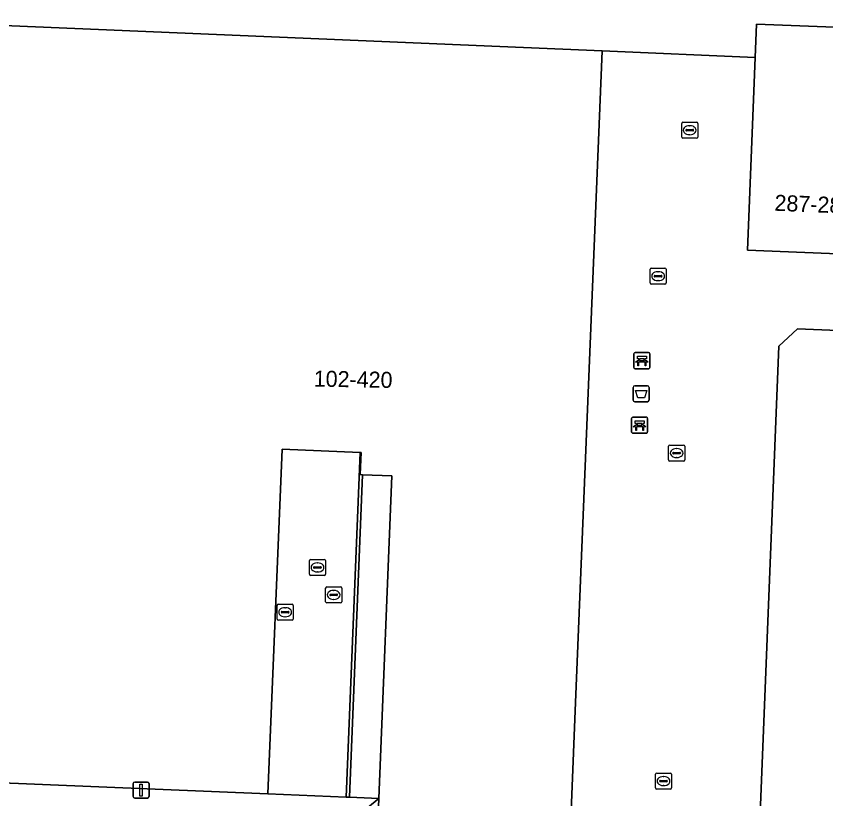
# Model space of a CAD drawing. Extents: x 160888 to 161385, y 386490 to 386908.
# Drawn here: x 161090.9 to 161141.4, y 386663.9 to 386712.7 of the extents above; entities that cross this region are included whole.
import ezdxf

# ---------------------------------------------------------------- set-up
doc = ezdxf.new("R2010")
doc.units = 0
for name, color, linetype in [('IMGEO_Afvalbak', 7, 'Continuous'), ('IMGEO_Bank', 7, 'Continuous'), ('IMGEO_Brandkraan', 7, 'Continuous'), ('IMGEO_Kolk', 7, 'Continuous'), ('IMGEO_Lichtmast', 7, 'Continuous'), ('IMGEO_Pand', 7, 'Continuous'), ('IMGEO_Pand_nummerreeks', 7, 'Continuous'), ('IMGEO_Rijbaan_lokaal_gesloten', 7, 'Continuous'), ('IMGEO_Rioolput', 7, 'Continuous'), ('IMGEO_Voetgangersgebied_open', 7, 'Continuous'), ('IMGEO_Voetpad_open', 7, 'Continuous')]:
    doc.layers.add(name, color=color, linetype=linetype)

msp = doc.modelspace()

# ---------------------------------------------------------------- linework, layer by layer
at = {"layer": 'IMGEO_Afvalbak'}
for p, q in [((161129.39, 386688.722), (161129.39, 386689.522)), ((161129.39, 386689.522), (161129.39, 386688.722)), ((161129.49, 386689.622), (161130.28, 386689.622)), ((161130.28, 386689.622), (161129.49, 386689.622)), ((161130.38, 386689.522), (161130.38, 386688.722)), ((161130.38, 386688.722), (161130.38, 386689.522)), ((161130.28, 386688.622), (161129.49, 386688.622)), ((161129.49, 386688.622), (161130.28, 386688.622))]:
    msp.add_line(p, q, dxfattribs=at)
msp.add_lwpolyline([(161129.533, 386689.336), (161130.237, 386689.336), (161130.088, 386688.866), (161129.682, 386688.866), (161129.533, 386689.336)], dxfattribs=at)
for centre, start, end in [((161129.49, 386689.522), 90, 180), ((161129.49, 386689.522), 90, 180), ((161130.28, 386689.522), 0, 90), ((161130.28, 386689.522), 360, 90), ((161129.49, 386688.722), 180, 270), ((161129.49, 386688.722), 180, 270), ((161130.28, 386688.722), 270, 0), ((161130.28, 386688.722), 270, 0)]:
    msp.add_arc(centre, 0.1, start, end, dxfattribs=at)
at = {"layer": 'IMGEO_Bank'}
for p, q in [((161129.508, 386691.686), (161130.349, 386691.686)), ((161130.349, 386691.686), (161129.508, 386691.686)), ((161129.433, 386690.761), (161129.433, 386691.602)), ((161129.433, 386691.602), (161129.433, 386690.761)), ((161129.742, 386691.192), (161129.742, 386691.298)), ((161129.786, 386691.298), (161129.786, 386691.192)), ((161130.074, 386691.304), (161129.792, 386691.304)), ((161129.792, 386691.186), (161130.074, 386691.186)), ((161130.08, 386691.192), (161130.08, 386691.298)), ((161130.124, 386691.298), (161130.124, 386691.192)), ((161130.433, 386691.611), (161130.433, 386690.77)), ((161130.433, 386690.77), (161130.433, 386691.611)), ((161130.358, 386690.686), (161129.517, 386690.686)), ((161129.517, 386690.686), (161130.358, 386690.686)), ((161130.13, 386691.084), (161129.737, 386691.084)), ((161129.366, 386687.659), (161130.207, 386687.659)), ((161130.207, 386687.659), (161129.366, 386687.659)), ((161129.291, 386686.734), (161129.291, 386687.575)), ((161129.291, 386687.575), (161129.291, 386686.734)), ((161129.6, 386687.165), (161129.6, 386687.271)), ((161129.644, 386687.271), (161129.644, 386687.165)), ((161129.932, 386687.277), (161129.65, 386687.277)), ((161129.65, 386687.159), (161129.932, 386687.159)), ((161129.938, 386687.165), (161129.938, 386687.271)), ((161129.982, 386687.271), (161129.982, 386687.165)), ((161130.291, 386687.584), (161130.291, 386686.743)), ((161130.291, 386686.743), (161130.291, 386687.584)), ((161130.216, 386686.659), (161129.375, 386686.659)), ((161129.375, 386686.659), (161130.216, 386686.659)), ((161129.988, 386687.057), (161129.595, 386687.057))]:
    msp.add_line(p, q, dxfattribs=at)
for points in [[(161129.68, 386691.084), (161129.538, 386691.084), (161129.65, 386691.186), (161129.736, 386691.186)], [(161129.736, 386691.304), (161129.65, 386691.304), (161129.65, 386691.465), (161130.213, 386691.465), (161130.213, 386691.304), (161130.13, 386691.304)], [(161130.13, 386691.186), (161130.213, 386691.186), (161130.325, 386691.084), (161130.186, 386691.084)], [(161129.73, 386691.077), (161129.73, 386690.87), (161129.687, 386690.87), (161129.687, 386691.077)], [(161130.18, 386691.077), (161130.18, 386690.87), (161130.136, 386690.87), (161130.136, 386691.077)], [(161129.538, 386687.057), (161129.396, 386687.057), (161129.508, 386687.159), (161129.594, 386687.159)], [(161129.594, 386687.277), (161129.508, 386687.277), (161129.508, 386687.438), (161130.071, 386687.438), (161130.071, 386687.277), (161129.988, 386687.277)], [(161129.988, 386687.159), (161130.071, 386687.159), (161130.183, 386687.057), (161130.044, 386687.057)], [(161129.588, 386687.05), (161129.588, 386686.843), (161129.545, 386686.843), (161129.545, 386687.05)], [(161130.038, 386687.05), (161130.038, 386686.843), (161129.994, 386686.843), (161129.994, 386687.05)]]:
    msp.add_lwpolyline(points, dxfattribs=at)
for centre, radius, start, end in [((161129.511, 386691.608), 0.0779, 92.4484, 184.2845), ((161129.511, 386691.608), 0.0779, 92.4484, 184.2845), ((161130.355, 386691.608), 0.0779, 2.4484, 94.2845), ((161130.355, 386691.608), 0.0779, 2.4484, 94.2845), ((161129.735, 386691.297), 0.00671, 2.8957, 87.1043), ((161129.735, 386691.193), 0.00671, 272.8957, 357.1043), ((161129.792, 386691.297), 0.00671, 92.8957, 177.1043), ((161129.792, 386691.193), 0.00671, 182.8957, 267.1043), ((161130.074, 386691.297), 0.00671, 2.8957, 87.1043), ((161130.074, 386691.193), 0.00671, 272.8957, 357.1043), ((161130.131, 386691.297), 0.00671, 92.8957, 177.1043), ((161130.131, 386691.193), 0.00671, 182.8957, 267.1043), ((161129.511, 386690.764), 0.0779, 182.4484, 274.2845), ((161129.511, 386690.764), 0.0779, 182.4484, 274.2845), ((161129.68, 386691.077), 0.00671, 2.8957, 87.1043), ((161129.737, 386691.077), 0.00671, 92.8957, 177.1043), ((161130.129, 386691.077), 0.00671, 2.8957, 87.1043), ((161130.186, 386691.077), 0.00671, 92.8957, 177.1043), ((161130.355, 386690.764), 0.0779, 272.4484, 4.2845), ((161130.355, 386690.764), 0.0779, 272.4484, 4.2845), ((161129.369, 386687.581), 0.0779, 92.4484, 184.2845), ((161129.369, 386687.581), 0.0779, 92.4484, 184.2845), ((161130.213, 386687.581), 0.0779, 2.4484, 94.2845), ((161130.213, 386687.581), 0.0779, 2.4484, 94.2845), ((161129.593, 386687.27), 0.00671, 2.8957, 87.1043), ((161129.593, 386687.166), 0.00671, 272.8957, 357.1043), ((161129.65, 386687.27), 0.00671, 92.8957, 177.1043), ((161129.65, 386687.166), 0.00671, 182.8957, 267.1043), ((161129.932, 386687.27), 0.00671, 2.8957, 87.1043), ((161129.932, 386687.166), 0.00671, 272.8957, 357.1043), ((161129.989, 386687.27), 0.00671, 92.8957, 177.1043), ((161129.989, 386687.166), 0.00671, 182.8957, 267.1043), ((161129.369, 386686.737), 0.0779, 182.4484, 274.2845), ((161129.369, 386686.737), 0.0779, 182.4484, 274.2845), ((161129.538, 386687.05), 0.00671, 2.8957, 87.1043), ((161129.595, 386687.05), 0.00671, 92.8957, 177.1043), ((161129.987, 386687.05), 0.00671, 2.8957, 87.1043), ((161130.044, 386687.05), 0.00671, 92.8957, 177.1043), ((161130.213, 386686.737), 0.0779, 272.4484, 4.2845), ((161130.213, 386686.737), 0.0779, 272.4484, 4.2845)]:
    msp.add_arc(centre, radius, start, end, dxfattribs=at)
at = {"layer": 'IMGEO_Brandkraan'}
for p, q in [((161109.214, 386677.871), (161109.214, 386678.723)), ((161109.289, 386678.797), (161110.141, 386678.797)), ((161109.702, 386678.577), (161109.727, 386678.577)), ((161110.215, 386678.723), (161110.215, 386677.871)), ((161109.473, 386678.291), (161109.473, 386678.303)), ((161109.911, 386678.254), (161109.513, 386678.254)), ((161109.516, 386678.34), (161109.914, 386678.34)), ((161109.957, 386678.303), (161109.957, 386678.291)), ((161110.141, 386677.797), (161109.289, 386677.797)), ((161109.725, 386678.017), (161109.7, 386678.017))]:
    msp.add_line(p, q, dxfattribs=at)
for points in [[(161109.214, 386677.871), (161109.214, 386678.723)], [(161109.289, 386678.797), (161110.141, 386678.797)], [(161110.215, 386678.723), (161110.215, 386677.871)], [(161110.141, 386677.797), (161109.289, 386677.797)]]:
    msp.add_lwpolyline(points, dxfattribs=at)
for centre, radius, start, end in [((161109.291, 386678.721), 0.0765, 91.552, 178.448), ((161109.291, 386678.721), 0.0765, 91.552, 178.448), ((161110.139, 386678.721), 0.0765, 1.552, 88.448), ((161110.139, 386678.721), 0.0765, 1.552, 88.448), ((161109.513, 386678.3), 0.0403, 85.8775, 175.7526), ((161109.51, 386678.29), 0.0366, 178.938, 274.7102), ((161109.914, 386678.297), 0.043, 264.8664, 352.4533), ((161109.918, 386678.302), 0.0386, 1.7309, 96.639), ((161109.291, 386677.873), 0.0765, 181.552, 268.448), ((161109.291, 386677.873), 0.0765, 181.552, 268.448), ((161110.139, 386677.873), 0.0765, 271.552, 358.448), ((161110.139, 386677.873), 0.0765, 271.552, 358.448)]:
    msp.add_arc(centre, radius, start, end, dxfattribs=at)
for centre, major_axis, ratio, start_param, end_param in [((161109.701, 386678.297), (-0.387, 0.002), 0.722429, 4.712389, 7.853982), ((161109.726, 386678.297), (-0.39, 0.002), 0.717154, 1.570796, 4.712389)]:
    msp.add_ellipse(centre, major_axis=major_axis, ratio=ratio, start_param=start_param, end_param=end_param, dxfattribs=at)
at = {"layer": 'IMGEO_Kolk'}
for p, q in [((161132.412, 386705.126), (161132.412, 386705.978)), ((161132.487, 386706.052), (161133.339, 386706.052)), ((161132.9, 386705.832), (161132.925, 386705.832)), ((161133.413, 386705.978), (161133.413, 386705.126)), ((161132.671, 386705.546), (161132.671, 386705.558)), ((161133.109, 386705.509), (161132.711, 386705.509)), ((161132.714, 386705.595), (161133.112, 386705.595)), ((161132.923, 386705.272), (161132.898, 386705.272)), ((161133.155, 386705.558), (161133.155, 386705.546)), ((161133.339, 386705.052), (161132.487, 386705.052)), ((161131.599, 386685.001), (161131.599, 386685.853)), ((161131.674, 386685.927), (161132.526, 386685.927)), ((161132.087, 386685.707), (161132.112, 386685.707)), ((161132.6, 386685.853), (161132.6, 386685.001)), ((161131.858, 386685.421), (161131.858, 386685.433)), ((161132.296, 386685.384), (161131.898, 386685.384)), ((161131.901, 386685.47), (161132.299, 386685.47)), ((161132.11, 386685.147), (161132.085, 386685.147)), ((161132.342, 386685.433), (161132.342, 386685.421)), ((161132.526, 386684.927), (161131.674, 386684.927)), ((161110.225, 386676.161), (161110.225, 386677.013)), ((161110.3, 386677.087), (161111.152, 386677.087)), ((161111.226, 386677.013), (161111.226, 386676.161)), ((161110.484, 386676.581), (161110.484, 386676.593)), ((161110.922, 386676.544), (161110.524, 386676.544)), ((161110.527, 386676.63), (161110.925, 386676.63)), ((161110.713, 386676.867), (161110.738, 386676.867)), ((161110.968, 386676.593), (161110.968, 386676.581)), ((161111.152, 386676.087), (161110.3, 386676.087)), ((161110.736, 386676.307), (161110.711, 386676.307)), ((161130.854, 386665.48), (161131.706, 386665.48)), ((161130.779, 386664.554), (161130.779, 386665.406)), ((161131.038, 386664.974), (161131.038, 386664.986)), ((161131.476, 386664.937), (161131.078, 386664.937)), ((161131.081, 386665.023), (161131.479, 386665.023)), ((161131.267, 386665.26), (161131.292, 386665.26)), ((161131.522, 386664.986), (161131.522, 386664.974)), ((161131.78, 386665.406), (161131.78, 386664.554)), ((161131.706, 386664.48), (161130.854, 386664.48)), ((161131.29, 386664.7), (161131.265, 386664.7))]:
    msp.add_line(p, q, dxfattribs=at)
for points in [[(161132.412, 386705.126), (161132.412, 386705.978)], [(161132.487, 386706.052), (161133.339, 386706.052)], [(161133.413, 386705.978), (161133.413, 386705.126)], [(161133.339, 386705.052), (161132.487, 386705.052)], [(161131.599, 386685.001), (161131.599, 386685.853)], [(161131.674, 386685.927), (161132.526, 386685.927)], [(161132.6, 386685.853), (161132.6, 386685.001)], [(161132.526, 386684.927), (161131.674, 386684.927)], [(161110.225, 386676.161), (161110.225, 386677.013)], [(161110.3, 386677.087), (161111.152, 386677.087)], [(161111.226, 386677.013), (161111.226, 386676.161)], [(161111.152, 386676.087), (161110.3, 386676.087)], [(161130.854, 386665.48), (161131.706, 386665.48)], [(161130.779, 386664.554), (161130.779, 386665.406)], [(161131.78, 386665.406), (161131.78, 386664.554)], [(161131.706, 386664.48), (161130.854, 386664.48)]]:
    msp.add_lwpolyline(points, dxfattribs=at)
for centre, radius, start, end in [((161132.489, 386705.976), 0.0765, 91.552, 178.448), ((161132.489, 386705.976), 0.0765, 91.552, 178.448), ((161133.337, 386705.976), 0.0765, 1.552, 88.448), ((161133.337, 386705.976), 0.0765, 1.552, 88.448), ((161132.711, 386705.555), 0.0403, 85.8775, 175.7526), ((161132.708, 386705.545), 0.0366, 178.938, 274.7102), ((161133.112, 386705.552), 0.043, 264.8664, 352.4533), ((161133.116, 386705.557), 0.0386, 1.7309, 96.639), ((161132.489, 386705.128), 0.0765, 181.552, 268.448), ((161132.489, 386705.128), 0.0765, 181.552, 268.448), ((161133.337, 386705.128), 0.0765, 271.552, 358.448), ((161133.337, 386705.128), 0.0765, 271.552, 358.448), ((161131.676, 386685.851), 0.0765, 91.552, 178.448), ((161131.676, 386685.851), 0.0765, 91.552, 178.448), ((161132.524, 386685.851), 0.0765, 1.552, 88.448), ((161132.524, 386685.851), 0.0765, 1.552, 88.448), ((161131.898, 386685.43), 0.0403, 85.8775, 175.7526), ((161131.895, 386685.42), 0.0366, 178.938, 274.7102), ((161132.299, 386685.427), 0.043, 264.8664, 352.4533), ((161132.303, 386685.432), 0.0386, 1.7309, 96.639), ((161131.676, 386685.003), 0.0765, 181.552, 268.448), ((161131.676, 386685.003), 0.0765, 181.552, 268.448), ((161132.524, 386685.003), 0.0765, 271.552, 358.448), ((161132.524, 386685.003), 0.0765, 271.552, 358.448), ((161110.302, 386677.011), 0.0765, 91.552, 178.448), ((161110.302, 386677.011), 0.0765, 91.552, 178.448), ((161111.15, 386677.011), 0.0765, 1.552, 88.448), ((161111.15, 386677.011), 0.0765, 1.552, 88.448), ((161110.524, 386676.59), 0.0403, 85.8775, 175.7526), ((161110.521, 386676.58), 0.0366, 178.938, 274.7102), ((161110.925, 386676.587), 0.043, 264.8664, 352.4533), ((161110.929, 386676.592), 0.0386, 1.7309, 96.639), ((161110.302, 386676.163), 0.0765, 181.552, 268.448), ((161110.302, 386676.163), 0.0765, 181.552, 268.448), ((161111.15, 386676.163), 0.0765, 271.552, 358.448), ((161111.15, 386676.163), 0.0765, 271.552, 358.448), ((161130.856, 386665.404), 0.0765, 91.552, 178.448), ((161130.856, 386665.404), 0.0765, 91.552, 178.448), ((161131.704, 386665.404), 0.0765, 1.552, 88.448), ((161131.704, 386665.404), 0.0765, 1.552, 88.448), ((161131.078, 386664.983), 0.0403, 85.8775, 175.7526), ((161131.075, 386664.973), 0.0366, 178.938, 274.7102), ((161131.479, 386664.98), 0.043, 264.8664, 352.4533), ((161131.483, 386664.985), 0.0386, 1.7309, 96.639), ((161130.856, 386664.556), 0.0765, 181.552, 268.448), ((161130.856, 386664.556), 0.0765, 181.552, 268.448), ((161131.704, 386664.556), 0.0765, 271.552, 358.448), ((161131.704, 386664.556), 0.0765, 271.552, 358.448)]:
    msp.add_arc(centre, radius, start, end, dxfattribs=at)
for centre, major_axis, ratio, start_param, end_param in [((161132.899, 386705.552), (-0.387, 0.002), 0.722429, 4.712389, 7.853982), ((161132.924, 386705.552), (-0.39, 0.002), 0.717154, 1.570796, 4.712389), ((161132.086, 386685.427), (-0.387, 0.002), 0.722429, 4.712389, 7.853982), ((161132.111, 386685.427), (-0.39, 0.002), 0.717154, 1.570796, 4.712389), ((161110.712, 386676.587), (-0.387, 0.002), 0.722429, 4.712389, 7.853982), ((161110.737, 386676.587), (-0.39, 0.002), 0.717154, 1.570796, 4.712389), ((161131.266, 386664.98), (-0.387, 0.002), 0.722429, 4.712389, 7.853982), ((161131.291, 386664.98), (-0.39, 0.002), 0.717154, 1.570796, 4.712389)]:
    msp.add_ellipse(centre, major_axis=major_axis, ratio=ratio, start_param=start_param, end_param=end_param, dxfattribs=at)
at = {"layer": 'IMGEO_Lichtmast'}
for p, q in [((161098.328, 386664.921), (161099.118, 386664.921)), ((161099.118, 386664.921), (161098.328, 386664.921)), ((161098.228, 386664.021), (161098.228, 386664.821)), ((161098.228, 386664.821), (161098.228, 386664.021)), ((161099.218, 386664.821), (161099.218, 386664.021)), ((161099.218, 386664.021), (161099.218, 386664.821)), ((161099.118, 386663.921), (161098.328, 386663.921)), ((161098.328, 386663.921), (161099.118, 386663.921))]:
    msp.add_line(p, q, dxfattribs=at)
msp.add_lwpolyline([(161098.648, 386664.796), (161098.798, 386664.796), (161098.798, 386664.046), (161098.648, 386664.046), (161098.648, 386664.796)], dxfattribs=at)
for centre, start, end in [((161098.328, 386664.821), 90, 180), ((161098.328, 386664.821), 90, 180), ((161099.118, 386664.821), 0, 90), ((161099.118, 386664.821), 360, 90), ((161098.328, 386664.021), 180, 270), ((161098.328, 386664.021), 180, 270), ((161099.118, 386664.021), 270, 0), ((161099.118, 386664.021), 270, 0)]:
    msp.add_arc(centre, 0.1, start, end, dxfattribs=at)
at = {"layer": 'IMGEO_Pand'}
for points in [[(161125.316, 386657.891), (161125.805, 386669.885), (161127.462, 386710.495), (161080.851, 386712.475), (161066.929, 386705.356), (161066.624, 386705.366), (161065.189, 386671.013), (161064.976, 386665.921), (161106.621, 386664.183), (161107.513, 386685.669), (161112.376, 386685.455), (161112.436, 386685.452), (161112.38, 386684.082), (161112.521, 386684.076), (161114.357, 386684.004), (161113.546, 386663.894), (161112.853, 386646.718)], [(161152.718, 386692.638), (161139.631, 386693.169), (161138.466, 386692.089), (161136.014, 386630.69), (161144.239, 386630.361)]]:
    msp.add_lwpolyline(points, dxfattribs=at)
msp.add_lwpolyline([(161147.81, 386709.63), (161147.892, 386711.738), (161137.065, 386712.159), (161136.985, 386710.09), (161136.801, 386705.368), (161136.518, 386698.078), (161143.664, 386697.789), (161147.34, 386697.641), (161147.455, 386700.577)], close=True, dxfattribs=at)
at = {"layer": 'IMGEO_Rijbaan_lokaal_gesloten'}
msp.add_lwpolyline([(161112.376, 386685.455), (161107.513, 386685.669), (161106.621, 386664.183), (161111.51, 386663.979)], close=True, dxfattribs=at)
at = {"layer": 'IMGEO_Rioolput'}
for p, q in [((161130.444, 386696.027), (161130.444, 386696.879)), ((161130.519, 386696.953), (161131.371, 386696.953)), ((161130.932, 386696.733), (161130.957, 386696.733)), ((161131.445, 386696.879), (161131.445, 386696.027)), ((161130.703, 386696.447), (161130.703, 386696.459)), ((161131.141, 386696.41), (161130.743, 386696.41)), ((161130.746, 386696.496), (161131.144, 386696.496)), ((161131.187, 386696.459), (161131.187, 386696.447)), ((161131.371, 386695.953), (161130.519, 386695.953)), ((161130.955, 386696.173), (161130.93, 386696.173)), ((161107.276, 386676.009), (161108.128, 386676.009)), ((161107.201, 386675.083), (161107.201, 386675.935)), ((161107.46, 386675.503), (161107.46, 386675.515)), ((161107.503, 386675.552), (161107.901, 386675.552)), ((161107.689, 386675.789), (161107.714, 386675.789)), ((161107.944, 386675.515), (161107.944, 386675.503)), ((161108.202, 386675.935), (161108.202, 386675.083)), ((161108.128, 386675.009), (161107.276, 386675.009)), ((161107.898, 386675.466), (161107.5, 386675.466)), ((161107.712, 386675.229), (161107.687, 386675.229))]:
    msp.add_line(p, q, dxfattribs=at)
for points in [[(161130.444, 386696.027), (161130.444, 386696.879)], [(161130.519, 386696.953), (161131.371, 386696.953)], [(161131.445, 386696.879), (161131.445, 386696.027)], [(161131.371, 386695.953), (161130.519, 386695.953)], [(161107.276, 386676.009), (161108.128, 386676.009)], [(161107.201, 386675.083), (161107.201, 386675.935)], [(161108.202, 386675.935), (161108.202, 386675.083)], [(161108.128, 386675.009), (161107.276, 386675.009)]]:
    msp.add_lwpolyline(points, dxfattribs=at)
for centre, radius, start, end in [((161130.521, 386696.877), 0.0765, 91.552, 178.448), ((161130.521, 386696.877), 0.0765, 91.552, 178.448), ((161131.369, 386696.877), 0.0765, 1.552, 88.448), ((161131.369, 386696.877), 0.0765, 1.552, 88.448), ((161130.743, 386696.456), 0.0403, 85.8775, 175.7526), ((161130.74, 386696.446), 0.0366, 178.938, 274.7102), ((161131.144, 386696.453), 0.043, 264.8664, 352.4533), ((161131.148, 386696.458), 0.0386, 1.7309, 96.639), ((161130.521, 386696.029), 0.0765, 181.552, 268.448), ((161130.521, 386696.029), 0.0765, 181.552, 268.448), ((161131.369, 386696.029), 0.0765, 271.552, 358.448), ((161131.369, 386696.029), 0.0765, 271.552, 358.448), ((161107.278, 386675.933), 0.0765, 91.552, 178.448), ((161107.278, 386675.933), 0.0765, 91.552, 178.448), ((161108.126, 386675.933), 0.0765, 1.552, 88.448), ((161108.126, 386675.933), 0.0765, 1.552, 88.448), ((161107.5, 386675.512), 0.0403, 85.8775, 175.7526), ((161107.497, 386675.502), 0.0366, 178.938, 274.7102), ((161107.901, 386675.509), 0.043, 264.8664, 352.4533), ((161107.905, 386675.514), 0.0386, 1.7309, 96.639), ((161107.278, 386675.085), 0.0765, 181.552, 268.448), ((161107.278, 386675.085), 0.0765, 181.552, 268.448), ((161108.126, 386675.085), 0.0765, 271.552, 358.448), ((161108.126, 386675.085), 0.0765, 271.552, 358.448)]:
    msp.add_arc(centre, radius, start, end, dxfattribs=at)
for centre, major_axis, ratio, start_param, end_param in [((161130.931, 386696.453), (-0.387, 0.002), 0.722429, 4.712389, 7.853982), ((161130.956, 386696.453), (-0.39, 0.002), 0.717154, 1.570796, 4.712389), ((161107.688, 386675.509), (-0.387, 0.002), 0.722429, 4.712389, 7.853982), ((161107.713, 386675.509), (-0.39, 0.002), 0.717154, 1.570796, 4.712389)]:
    msp.add_ellipse(centre, major_axis=major_axis, ratio=ratio, start_param=start_param, end_param=end_param, dxfattribs=at)
at = {"layer": 'IMGEO_Voetgangersgebied_open'}
for points in [[(161161.551, 386723.521), (161138.885, 386724.445), (161138.981, 386726.813), (161089.335, 386728.855), (161089.223, 386726.344), (161081.411, 386726.666), (161068.128, 386734.901), (161067.82, 386734.914), (161066.624, 386705.366), (161066.929, 386705.356), (161080.851, 386712.475), (161127.462, 386710.495), (161136.985, 386710.09), (161137.065, 386712.159), (161147.892, 386711.738)], [(161143.664, 386697.789), (161136.518, 386698.078), (161136.801, 386705.368), (161136.985, 386710.09), (161127.462, 386710.495), (161125.805, 386669.885), (161125.316, 386657.891), (161124.93, 386648.428), (161124.542, 386638.918), (161124.235, 386631.392), (161123.653, 386617.125), (161129.234, 386616.884), (161129.102, 386613.11), (161130.741, 386613.029), (161130.314, 386602.572), (161129.817, 386590.42), (161129.528, 386583.353), (161129.239, 386576.285), (161128.539, 386559.143), (161131.001, 386561.219), (161139.877, 386568.704), (161143.412, 386571.685)], [(161144.239, 386630.361), (161136.014, 386630.69), (161138.466, 386692.089), (161139.631, 386693.169), (161152.718, 386692.638)]]:
    msp.add_lwpolyline(points, dxfattribs=at)
at = {"layer": 'IMGEO_Voetpad_open'}
msp.add_lwpolyline([(161046.39, 386664.154), (161046.13, 386658.175), (161046.865, 386658.1), (161047.155, 386663.993), (161110.493, 386661.403), (161113.546, 386663.894), (161111.71, 386663.971), (161111.51, 386663.979), (161106.621, 386664.183), (161064.976, 386665.921), (161063.364, 386665.987), (161063.573, 386671.097), (161065.189, 386671.013), (161066.624, 386705.366), (161067.82, 386734.914)], dxfattribs=at)
for points in [[(161112.521, 386684.076), (161112.38, 386684.082), (161112.436, 386685.452), (161112.376, 386685.455), (161111.51, 386663.979), (161111.71, 386663.971)], [(161114.357, 386684.004), (161112.521, 386684.076), (161111.71, 386663.971), (161113.546, 386663.894)], [(161112.255, 386631.87), (161112.378, 386634.915), (161112.559, 386639.396), (161112.621, 386640.934), (161112.853, 386646.718), (161113.546, 386663.894), (161110.493, 386661.403), (161107.744, 386593.603), (161107.72, 386592.866), (161107.346, 386581.714), (161048.595, 386584.064), (161046.972, 386584.164), (161046.888, 386581.503), (161050.87, 386581.374), (161050.874, 386581.474), (161062.171, 386581.019), (161074.316, 386580.531), (161084.022, 386580.14), (161091.136, 386579.854), (161110.116, 386579.09), (161110.319, 386584.108), (161110.606, 386591.176), (161111.098, 386603.328)]]:
    msp.add_lwpolyline(points, close=True, dxfattribs=at)

# ---------------------------------------------------------------- texts
at = {"layer": 'IMGEO_Pand_nummerreeks'}
for s, rotation, p in [('287-289', 357.6853, (161138.181, 386700.533)), ('102-420', 358.9744, (161109.475, 386689.57))]:
    msp.add_text(s, height=1, rotation=rotation, dxfattribs=at).set_placement(p)

doc.saveas('drawing.dxf')
